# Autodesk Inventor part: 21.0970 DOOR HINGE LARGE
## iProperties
Created: 2010-07
Part Number: 21.0970 DOOR HINGE LARGE
Document SubType Name: Modeling
Designer: Administrator
Density: 1 g/cm^3
Author: Administrator
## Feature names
1. Extrusion1
2. Chamfer1
